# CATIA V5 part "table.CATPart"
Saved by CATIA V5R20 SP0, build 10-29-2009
Part number: table
Bounding box of the stored display mesh (mm): x -110 to 110, y -60 to 60, z -100 to 20
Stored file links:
  C:\Users\bensf\Desktop\bouthaina\table.CATPart
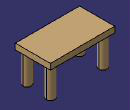
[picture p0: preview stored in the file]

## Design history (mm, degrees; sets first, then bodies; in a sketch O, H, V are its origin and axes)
Body1 (main body)
  Sketch1 on xy-plane, origin (0, 0, 0), H (1, 0, 0), V (0, 1, 0)
    line L1 (110, 60) -> (110, -60)
    line L2 (110, -60) -> (-110, -60)
    line L3 (-110, -60) -> (-110, 60)
    line L4 (-110, 60) -> (110, 60)
    vertical: L1 V, L3 V
    horizontal: L2 H, L4 H
    equidistance: L1 L3 O, L2 L4 O
  Pad1: profile Sketch1, direction (0, 0, 1), length 20
  Sketch2 on start face of Pad1, origin (0, 0, 0), H (1, 0, 0), V (0, -1, 0)
    circle A1 centre (90, 40) radius 14.1421
    circle A2 centre (-90, 40) radius 14.1421
    circle A3 centre (90, -40) radius 14.1421
    circle A4 centre (-90, -40) radius 14.1421
    symmetry: A1 A2 V, A1 A3 H, A2 A4 H
  Pad2: profile Sketch2, direction (0, 0, -1), length 100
